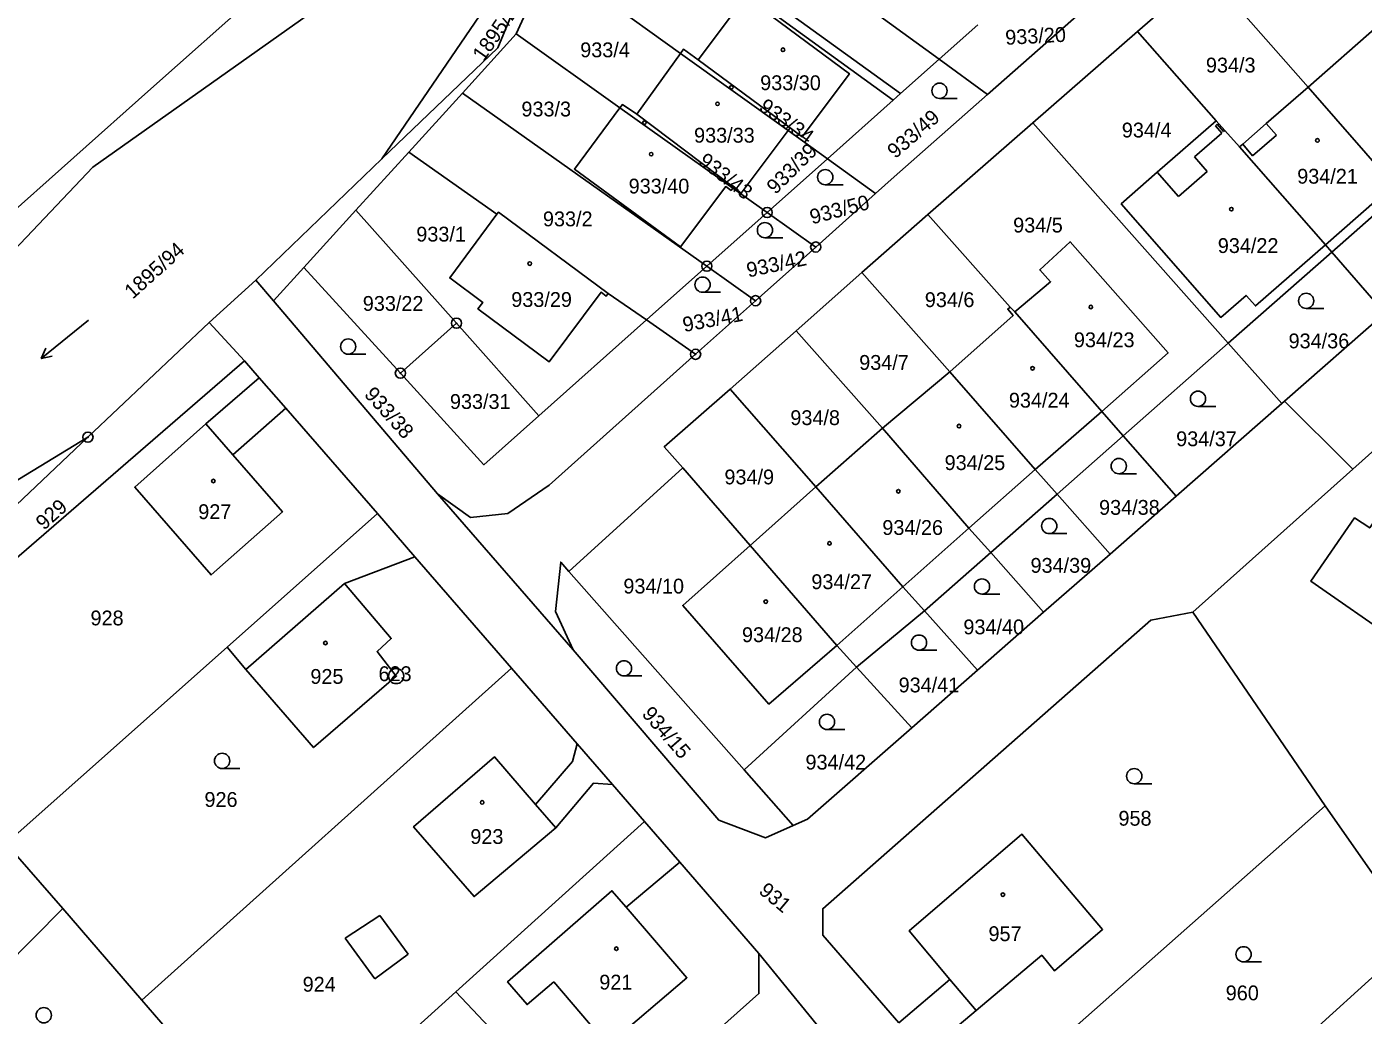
# Model space of a CAD drawing. Extents: x -587171 to -555306, y -1167727 to -1074732.
# Drawn here: x -560285.3 to -560153.7, y -1077555.8 to -1077458.5 of the extents above; entities that cross this region are included whole.
import ezdxf

# ---------------------------------------------------------------- set-up
doc = ezdxf.new("R2010")
doc.units = 0
for name, color, linetype in [('Hranice parcel', 7, 'Continuous'), ('Parcelní čísla', 7, 'Continuous'), ('Vnitřní kresba', 7, 'Continuous'), ('Značky bodu BP', 7, 'Continuous'), ('Značky budov', 7, 'Continuous'), ('Značky kultur', 7, 'Continuous')]:
    doc.layers.add(name, color=color, linetype=linetype)

msp = doc.modelspace()

# ---------------------------------------------------------------- linework, layer by layer
at = {"layer": 'Hranice parcel'}
for p, q in [((-560195.5, -1077461.65), (-560227.6, -1077438.32)), ((-560229.75, -1077443), (-560199.31, -1077465.04)), ((-560200.02, -1077465.68), (-560230.15, -1077443.87)), ((-560237.17, -1077459.16), (-560233.82, -1077451.86)), ((-560220.97, -1077461.08), (-560233.82, -1077451.86)), ((-560273.13, -1077464.57), (-560260.86, -1077453.64)), ((-560175.99, -1077458.92), (-560169.18, -1077453.02)), ((-560169.18, -1077453.02), (-560159.18, -1077464.39)), ((-560190.74, -1077465.12), (-560179.7, -1077455.38)), ((-560195.5, -1077461.65), (-560191.69, -1077458.26)), ((-560186.28, -1077467.93), (-560175.99, -1077458.92)), ((-560175.99, -1077458.92), (-560168.22, -1077467.71)), ((-560159.18, -1077464.39), (-560152.39, -1077458.44)), ((-560242.45, -1077464.98), (-560237.17, -1077459.16)), ((-560226.94, -1077466.44), (-560237.17, -1077459.16)), ((-560225.28, -1077467.06), (-560220.97, -1077461.08)), ((-560210.38, -1077468.68), (-560220.97, -1077461.08)), ((-560219.22, -1077461.72), (-560210.18, -1077468.42)), ((-560199.31, -1077465.04), (-560195.5, -1077461.65)), ((-560195.5, -1077461.65), (-560190.74, -1077465.12)), ((-560273.13, -1077464.57), (-560298.78, -1077487.41)), ((-560247.74, -1077470.8), (-560242.45, -1077464.98)), ((-560218.38, -1077482.04), (-560242.45, -1077464.98)), ((-560200.02, -1077465.68), (-560199.31, -1077465.04)), ((-560215.82, -1077474.34), (-560226.94, -1077466.44)), ((-560206.5, -1077471.46), (-560200.02, -1077465.68)), ((-560225.28, -1077467.06), (-560215.76, -1077474.25)), ((-560196.61, -1077476.96), (-560186.28, -1077467.93)), ((-560186.28, -1077467.93), (-560167.04, -1077489.63)), ((-560210.18, -1077468.42), (-560210.38, -1077468.68)), ((-560210.38, -1077468.68), (-560206.5, -1077471.46)), ((-560252.95, -1077476.52), (-560247.74, -1077470.8)), ((-560239.05, -1077476.93), (-560247.74, -1077470.8)), ((-560165.93, -1077470.29), (-560157.48, -1077479.93)), ((-560250.37, -1077471.48), (-560262.78, -1077483.42)), ((-560212.44, -1077476.75), (-560206.5, -1077471.46)), ((-560206.5, -1077471.46), (-560201.76, -1077474.87)), ((-560154.78, -1077502.03), (-560122.01, -1077472.74)), ((-560215.76, -1077474.25), (-560215.82, -1077474.34)), ((-560212.44, -1077476.75), (-560215.82, -1077474.34)), ((-560156.85, -1077480.65), (-560150.14, -1077474.73)), ((-560201.76, -1077474.87), (-560207.66, -1077480.15)), ((-560258.07, -1077482.16), (-560252.95, -1077476.52)), ((-560252.95, -1077476.52), (-560243.03, -1077487.66)), ((-560218.38, -1077482.04), (-560212.44, -1077476.75)), ((-560207.66, -1077480.15), (-560212.44, -1077476.75)), ((-560203.12, -1077482.67), (-560196.61, -1077476.96)), ((-560196.61, -1077476.96), (-560188.5, -1077486.06)), ((-560156.85, -1077480.65), (-560157.48, -1077479.93)), ((-560207.66, -1077480.15), (-560213.58, -1077485.44)), ((-560167.04, -1077489.63), (-560156.85, -1077480.65)), ((-560156.85, -1077480.65), (-560151.61, -1077486.65)), ((-560261.05, -1077485.45), (-560258.07, -1077482.16)), ((-560258.07, -1077482.16), (-560248.56, -1077492.58)), ((-560224.31, -1077487.32), (-560218.38, -1077482.04)), ((-560213.58, -1077485.44), (-560218.38, -1077482.04)), ((-560209.6, -1077488.41), (-560203.12, -1077482.67)), ((-560203.12, -1077482.67), (-560194.46, -1077492.43)), ((-560262.78, -1077483.42), (-560267.37, -1077487.58)), ((-560261.05, -1077485.45), (-560262.78, -1077483.42)), ((-560224.31, -1077487.32), (-560228.1, -1077484.74)), ((-560244.9, -1077504.45), (-560261.05, -1077485.45)), ((-560213.58, -1077485.44), (-560219.49, -1077490.72)), ((-560188.5, -1077486.06), (-560188.04, -1077486.53)), ((-560188.04, -1077486.53), (-560179.49, -1077496.34)), ((-560151.61, -1077486.65), (-560161.51, -1077495.35)), ((-560267.37, -1077487.58), (-560279.32, -1077498.88)), ((-560263.92, -1077491.36), (-560267.37, -1077487.58)), ((-560248.56, -1077492.58), (-560243.03, -1077487.66)), ((-560243.03, -1077487.66), (-560234.91, -1077496.77)), ((-560234.91, -1077496.77), (-560224.31, -1077487.32)), ((-560219.49, -1077490.72), (-560224.31, -1077487.32)), ((-560216.09, -1077494.16), (-560209.6, -1077488.41)), ((-560209.6, -1077488.41), (-560201.09, -1077497.99)), ((-560177.38, -1077498.75), (-560167.04, -1077489.63)), ((-560167.04, -1077489.63), (-560161.77, -1077495.57)), ((-560263.92, -1077491.36), (-560300.86, -1077523.32)), ((-560262.47, -1077493.02), (-560263.92, -1077491.36)), ((-560219.49, -1077490.72), (-560233.92, -1077503.62)), ((-560259.85, -1077496.04), (-560262.47, -1077493.02)), ((-560201.09, -1077497.99), (-560194.46, -1077492.43)), ((-560216.09, -1077494.16), (-560207.66, -1077503.77)), ((-560161.77, -1077495.57), (-560172.18, -1077504.7)), ((-560161.51, -1077495.35), (-560161.77, -1077495.57)), ((-560250.82, -1077506.4), (-560259.85, -1077496.04)), ((-560179.49, -1077496.34), (-560177.38, -1077498.75)), ((-560207.66, -1077503.77), (-560201.09, -1077497.99)), ((-560279.32, -1077498.88), (-560302.8, -1077521.08)), ((-560183.9, -1077504.49), (-560177.38, -1077498.75)), ((-560177.38, -1077498.75), (-560172.18, -1077504.7)), ((-560231.97, -1077512.1), (-560220.76, -1077501.91)), ((-560220.76, -1077501.91), (-560214.1, -1077509.55)), ((-560170.54, -1077516.12), (-560154.78, -1077502.03)), ((-560231.56, -1077519.83), (-560244.9, -1077504.45)), ((-560214.1, -1077509.55), (-560207.66, -1077503.77)), ((-560190.43, -1077510.25), (-560183.9, -1077504.49)), ((-560183.9, -1077504.49), (-560178.67, -1077510.39)), ((-560172.18, -1077504.7), (-560178.67, -1077510.39)), ((-560250.82, -1077506.4), (-560265.62, -1077519.56)), ((-560247.12, -1077510.67), (-560250.82, -1077506.4)), ((-560214.1, -1077509.55), (-560205.58, -1077519.4)), ((-560196.95, -1077516), (-560190.43, -1077510.25)), ((-560190.43, -1077510.25), (-560185.22, -1077516.13)), ((-560237.62, -1077521.64), (-560247.12, -1077510.67)), ((-560178.67, -1077510.39), (-560185.22, -1077516.13)), ((-560231.97, -1077512.1), (-560214.71, -1077531.65)), ((-560203.65, -1077521.52), (-560196.95, -1077516)), ((-560196.95, -1077516), (-560191.74, -1077521.84)), ((-560185.22, -1077516.13), (-560191.74, -1077521.84)), ((-560170.54, -1077516.12), (-560157.51, -1077535.21)), ((-560203.65, -1077521.52), (-560205.58, -1077519.4)), ((-560265.62, -1077519.56), (-560287.37, -1077538.9)), ((-560237.62, -1077521.64), (-560274.02, -1077554.33)), ((-560231.16, -1077529.09), (-560237.62, -1077521.64)), ((-560214.71, -1077531.65), (-560203.65, -1077521.52)), ((-560203.65, -1077521.52), (-560198.21, -1077527.51)), ((-560191.74, -1077521.84), (-560198.21, -1077527.51)), ((-560227.68, -1077533.09), (-560231.16, -1077529.09)), ((-560209.87, -1077537.13), (-560214.71, -1077531.65)), ((-560224.51, -1077536.75), (-560227.68, -1077533.09)), ((-560191.75, -1077565.49), (-560157.51, -1077535.21)), ((-560157.51, -1077535.21), (-560148.96, -1077547.42)), ((-560224.51, -1077536.75), (-560243.11, -1077553.53)), ((-560221.04, -1077540.75), (-560224.51, -1077536.75)), ((-560281.79, -1077545.31), (-560287.37, -1077538.9)), ((-560213.26, -1077549.74), (-560221.04, -1077540.75)), ((-560274.02, -1077554.33), (-560281.79, -1077545.31)), ((-560199.49, -1077556.57), (-560206.96, -1077547.95)), ((-560181.09, -1077577.69), (-560148.82, -1077548.43)), ((-560199.75, -1077566.27), (-560213.26, -1077549.74)), ((-560243.11, -1077553.53), (-560260.72, -1077569.43)), ((-560270.26, -1077558.67), (-560274.02, -1077554.33))]:
    msp.add_line(p, q, dxfattribs=at)
for points in [[(-560214.76, -1077410.16), (-560235.05, -1077451.08), (-560238.97, -1077460.52), (-560250.37, -1077471.48)], [(-560344.11, -1077542.98), (-560322.5, -1077519.89), (-560300.89, -1077495.53), (-560278.85, -1077472.29), (-560254.7, -1077455.13), (-560250.95, -1077451.74), (-560235.79, -1077431.89)], [(-560231.69, -1077442.28), (-560235.75, -1077449.99), (-560250.37, -1077471.48)], [(-560219.22, -1077461.72), (-560214.58, -1077455.47), (-560204.35, -1077463.08), (-560209.01, -1077469.29), (-560210.18, -1077468.42)], [(-560220.97, -1077461.08), (-560220.67, -1077460.65), (-560219.22, -1077461.72)], [(-560190.74, -1077465.12), (-560199.94, -1077473.24), (-560201.76, -1077474.87)], [(-560165.93, -1077470.29), (-560165.62, -1077470.03), (-560163.3, -1077467.99), (-560159.18, -1077464.39)], [(-560159.18, -1077464.39), (-560150.76, -1077474.02), (-560150.14, -1077474.73)], [(-560215.82, -1077474.34), (-560215.99, -1077474.58), (-560216.52, -1077474.2), (-560220.97, -1077480.14), (-560231.42, -1077472.47), (-560226.94, -1077466.44)], [(-560226.94, -1077466.44), (-560226.7, -1077466.12), (-560225.28, -1077467.06)], [(-560157.48, -1077479.93), (-560164.36, -1077485.95), (-560165.28, -1077484.91), (-560167.78, -1077487.09), (-560177.57, -1077475.9), (-560174.03, -1077472.79), (-560168.22, -1077467.71)], [(-560168.22, -1077467.71), (-560167.37, -1077468.66), (-560165.93, -1077470.29)], [(-560215.76, -1077474.25), (-560214.99, -1077474.83), (-560210.38, -1077468.68)], [(-560228.1, -1077484.74), (-560228.28, -1077484.99), (-560228.8, -1077484.6), (-560233.91, -1077491.47), (-560240.93, -1077486.23), (-560240.45, -1077485.61), (-560243.7, -1077483.2), (-560239.05, -1077476.93)], [(-560239.05, -1077476.93), (-560238.9, -1077476.73), (-560228.1, -1077484.74)], [(-560188.04, -1077486.53), (-560184.54, -1077483.57), (-560185.61, -1077482.4), (-560182.62, -1077479.63), (-560172.96, -1077490.59), (-560179.49, -1077496.34)], [(-560194.46, -1077492.43), (-560188.22, -1077486.88), (-560188.75, -1077486.27), (-560188.5, -1077486.06)], [(-560262.47, -1077493.02), (-560267.72, -1077497.56), (-560274.71, -1077503.79), (-560267.19, -1077512.45), (-560260.18, -1077506.22), (-560265.06, -1077500.61), (-560259.85, -1077496.04)], [(-560248.56, -1077492.58), (-560240.33, -1077501.59), (-560234.91, -1077496.77)], [(-560194.46, -1077492.43), (-560186.04, -1077502.08), (-560183.9, -1077504.49)], [(-560220.76, -1077501.91), (-560222.57, -1077499.83), (-560216.09, -1077494.16)], [(-560154.78, -1077502.03), (-560155.11, -1077501.7), (-560161.51, -1077495.35)], [(-560201.09, -1077497.99), (-560192.57, -1077507.84), (-560190.43, -1077510.25)], [(-560279.32, -1077498.88), (-560322.75, -1077525.36), (-560344.11, -1077542.98)], [(-560147.31, -1077502.53), (-560148.82, -1077501.54), (-560153.11, -1077507.82), (-560154.6, -1077506.84), (-560158.9, -1077513.07), (-560150.41, -1077518.96), (-560145.99, -1077512.72), (-560144.51, -1077513.73), (-560140.23, -1077507.47)], [(-560233.92, -1077503.62), (-560237.97, -1077506.39), (-560241.66, -1077506.79), (-560244.9, -1077504.45)], [(-560207.66, -1077503.77), (-560199.08, -1077513.62), (-560196.95, -1077516)], [(-560205.58, -1077519.4), (-560212.27, -1077525.17), (-560220.76, -1077515.46), (-560214.1, -1077509.55)], [(-560265.62, -1077519.56), (-560263.78, -1077521.77), (-560257.11, -1077529.45), (-560248.97, -1077522.41), (-560250.85, -1077520), (-560249.45, -1077518.72), (-560254.07, -1077513.3), (-560247.12, -1077510.67)], [(-560231.56, -1077519.83), (-560233.27, -1077516.04), (-560232.77, -1077511.18), (-560231.97, -1077512.1)], [(-560206.96, -1077547.95), (-560206.97, -1077545.34), (-560174.65, -1077516.92), (-560170.54, -1077516.12)], [(-560209.87, -1077537.13), (-560212.61, -1077538.36), (-560217.19, -1077536.61), (-560231.56, -1077519.83)], [(-560198.21, -1077527.51), (-560208.48, -1077536.51), (-560209.87, -1077537.13)], [(-560231.16, -1077529.09), (-560231.6, -1077530.83), (-560235.25, -1077535.05), (-560239.29, -1077530.38), (-560247.26, -1077537.26), (-560241.3, -1077544.14), (-560233.24, -1077537.37), (-560229.55, -1077532.97), (-560227.68, -1077533.09)], [(-560196.87, -1077559.58), (-560191.86, -1077555.36), (-560185.4, -1077549.92), (-560184.14, -1077551.46), (-560179.41, -1077547.36), (-560187.35, -1077537.99), (-560198.47, -1077547.52), (-560194.44, -1077552.3), (-560199.49, -1077556.57)], [(-560243.11, -1077553.53), (-560233.23, -1077563.99), (-560228.13, -1077558.76), (-560220.34, -1077552.13), (-560226.33, -1077545.19), (-560221.04, -1077540.75)], [(-560285.34, -1077573.49), (-560297.87, -1077561.55), (-560287.62, -1077551.2), (-560281.79, -1077545.31)], [(-560247.77, -1077584.47), (-560213.26, -1077553.69), (-560213.26, -1077549.74)]]:
    msp.add_lwpolyline(points, dxfattribs=at)
at = {"layer": 'Vnitřní kresba'}
for p, q in [((-560168.12, -1077468.06), (-560168.3, -1077468.22)), ((-560168.3, -1077468.22), (-560167.68, -1077468.93)), ((-560167.5, -1077468.77), (-560168.12, -1077468.06)), ((-560162.3, -1077469.12), (-560163.3, -1077467.99)), ((-560167.68, -1077468.93), (-560170.37, -1077471.28)), ((-560167.37, -1077468.66), (-560167.5, -1077468.77)), ((-560164.64, -1077471.16), (-560162.3, -1077469.12)), ((-560165.62, -1077470.03), (-560164.64, -1077471.16)), ((-560170.37, -1077471.28), (-560169.11, -1077472.71)), ((-560171.94, -1077475.18), (-560174.03, -1077472.79)), ((-560169.11, -1077472.71), (-560171.94, -1077475.18)), ((-560150.76, -1077474.02), (-560157.48, -1077479.93)), ((-560179.49, -1077496.34), (-560186.04, -1077502.08)), ((-560267.72, -1077497.56), (-560265.06, -1077500.61)), ((-560186.04, -1077502.08), (-560192.57, -1077507.84)), ((-560192.57, -1077507.84), (-560199.08, -1077513.62)), ((-560254.07, -1077513.3), (-560263.78, -1077521.77)), ((-560199.08, -1077513.62), (-560205.58, -1077519.4)), ((-560235.25, -1077535.05), (-560233.24, -1077537.37)), ((-560254.01, -1077548.22), (-560250.59, -1077546)), ((-560250.59, -1077546), (-560247.78, -1077549.81)), ((-560251.08, -1077552.25), (-560254.01, -1077548.22)), ((-560247.78, -1077549.81), (-560251.08, -1077552.25)), ((-560194.44, -1077552.3), (-560191.86, -1077555.36)), ((-560233.46, -1077552.54), (-560228.13, -1077558.76))]:
    msp.add_line(p, q, dxfattribs=at)
msp.add_lwpolyline([(-560233.46, -1077552.54), (-560236.08, -1077554.78), (-560238.01, -1077552.53), (-560227.73, -1077543.56), (-560226.33, -1077545.19)], dxfattribs=at)
at = {"layer": 'Značky bodu BP'}
for centre, radius in [((-560212.44, -1077476.75), 0.5), ((-560212.44, -1077476.75), 0.0303), ((-560207.66, -1077480.15), 0.5), ((-560207.66, -1077480.15), 0.0303), ((-560218.38, -1077482.04), 0.5), ((-560218.38, -1077482.04), 0.0303), ((-560213.58, -1077485.44), 0.5), ((-560213.58, -1077485.44), 0.0303), ((-560243.03, -1077487.66), 0.5), ((-560243.03, -1077487.66), 0.0303), ((-560219.49, -1077490.72), 0.5), ((-560219.49, -1077490.72), 0.0303), ((-560248.56, -1077492.58), 0.5), ((-560248.56, -1077492.58), 0.0303), ((-560279.32, -1077498.88), 0.5), ((-560279.32, -1077498.88), 0.0303), ((-560248.97, -1077522.41), 0.75), ((-560248.97, -1077522.41), 0.03)]:
    msp.add_circle(centre, radius, dxfattribs=at)
at = {"layer": 'Značky budov'}
for centre in [(-560210.89, -1077460.72), (-560215.96, -1077464.42), (-560217.33, -1077466.05), (-560224.52, -1077467.9), (-560158.26, -1077469.65), (-560223.86, -1077471.01), (-560166.73, -1077476.42), (-560235.82, -1077481.78), (-560180.57, -1077486.06), (-560186.31, -1077492.1), (-560193.55, -1077497.79), (-560266.97, -1077503.2), (-560199.52, -1077504.21), (-560206.3, -1077509.34), (-560212.58, -1077515.08), (-560255.94, -1077519.16), (-560240.51, -1077534.86), (-560189.23, -1077543.94), (-560227.29, -1077549.27)]:
    msp.add_circle(centre, 0.175, dxfattribs=at)
at = {"layer": 'Značky kultur'}
for p, q in [((-560195.47, -1077465.51), (-560193.72, -1077465.51)), ((-560206.72, -1077474.02), (-560204.97, -1077474.02)), ((-560212.66, -1077479.24), (-560210.91, -1077479.24)), ((-560218.8, -1077484.61), (-560217.05, -1077484.61)), ((-560159.37, -1077486.2), (-560157.62, -1077486.2)), ((-560279.26, -1077487.36), (-560283.92, -1077491.13)), ((-560283.92, -1077491.13), (-560283.48, -1077490.13)), ((-560283.92, -1077491.13), (-560282.84, -1077490.91)), ((-560253.7, -1077490.71), (-560251.95, -1077490.71)), ((-560170.02, -1077495.85), (-560168.27, -1077495.85)), ((-560177.82, -1077502.48), (-560176.07, -1077502.48)), ((-560184.67, -1077508.38), (-560182.92, -1077508.38)), ((-560191.29, -1077514.34), (-560189.54, -1077514.34)), ((-560197.49, -1077519.87), (-560195.74, -1077519.87)), ((-560226.54, -1077522.4), (-560224.79, -1077522.4)), ((-560206.55, -1077527.68), (-560204.8, -1077527.68)), ((-560266.11, -1077531.52), (-560264.36, -1077531.52)), ((-560176.3, -1077533.02), (-560174.55, -1077533.02)), ((-560165.53, -1077550.57), (-560163.78, -1077550.57))]:
    msp.add_line(p, q, dxfattribs=at)
for centre in [(-560195.47, -1077464.76), (-560206.72, -1077473.27), (-560212.66, -1077478.49), (-560218.8, -1077483.86), (-560159.37, -1077485.45), (-560253.7, -1077489.96), (-560170.02, -1077495.1), (-560177.82, -1077501.73), (-560184.67, -1077507.63), (-560191.29, -1077513.59), (-560197.49, -1077519.12), (-560226.54, -1077521.65), (-560206.55, -1077526.93), (-560266.11, -1077530.77), (-560176.3, -1077532.27), (-560165.53, -1077549.82), (-560283.67, -1077555.82)]:
    msp.add_circle(centre, 0.75, dxfattribs=at)

# ---------------------------------------------------------------- texts
at = {"layer": 'Parcelní čísla'}
for s, rotation, p in [('1895/20', 55, (-560240.37, -1077461.96)), ('933/20', 3, (-560188.96, -1077460.24)), ('933/34', 324, (-560213.36, -1077466.59)), ('933/49', 41, (-560199.83, -1077471.51)), ('933/39', 45, (-560211.62, -1077475.04)), ('933/43', 322, (-560219.32, -1077471.9)), ('933/50', 15, (-560208.02, -1077477.93)), ('1895/94', 42, (-560274.92, -1077485.35)), ('933/42', 12, (-560214.3, -1077483.16)), ('933/41', 11, (-560220.61, -1077488.54)), ('933/38', 312, (-560252.2, -1077494.73)), ('929', 42, (-560283.65, -1077508.11)), ('934/15', 311, (-560224.86, -1077526.19)), ('931', 320, (-560213.36, -1077543.73))]:
    msp.add_text(s, height=1.46, rotation=rotation, dxfattribs=at).set_placement(p)
for s, p in [('933/4', (-560230.85, -1077461.46)), ('934/3', (-560169.24, -1077462.96)), ('933/30', (-560213.13, -1077464.7)), ('933/3', (-560236.64, -1077467.29)), ('934/4', (-560177.52, -1077469.36)), ('933/33', (-560219.64, -1077469.87)), ('933/40', (-560226.08, -1077474.88)), ('934/21', (-560160.25, -1077473.91)), ('933/2', (-560234.52, -1077478.11)), ('934/5', (-560188.22, -1077478.72)), ('933/1', (-560246.99, -1077479.61)), ('934/22', (-560168.07, -1077480.74)), ('933/22', (-560252.26, -1077486.44)), ('933/29', (-560237.64, -1077486.05)), ('934/6', (-560196.92, -1077486.07)), ('934/23', (-560182.24, -1077490.02)), ('934/36', (-560161.1, -1077490.13)), ('934/7', (-560203.38, -1077492.25)), ('934/24', (-560188.64, -1077495.97)), ('933/31', (-560243.68, -1077496.1)), ('934/8', (-560210.16, -1077497.69)), ('934/37', (-560172.17, -1077499.77)), ('934/25', (-560194.97, -1077502.12)), ('934/9', (-560216.65, -1077503.53)), ('934/38', (-560179.76, -1077506.53)), ('927', (-560268.46, -1077506.95)), ('934/26', (-560201.1, -1077508.51)), ('934/39', (-560186.51, -1077512.24)), ('934/10', (-560226.6, -1077514.28)), ('934/27', (-560208.09, -1077513.85)), ('928', (-560279.07, -1077517.42)), ('934/40', (-560193.12, -1077518.3)), ('934/28', (-560214.92, -1077519.07)), ('925', (-560257.42, -1077523.18)), ('934/41', (-560199.5, -1077524.02)), ('934/42', (-560208.67, -1077531.62)), ('926', (-560267.85, -1077535.3)), ('958', (-560177.85, -1077537.15)), ('923', (-560241.67, -1077538.95)), ('957', (-560190.65, -1077548.52)), ('924', (-560258.18, -1077553.5)), ('921', (-560228.97, -1077553.29)), ('960', (-560167.29, -1077554.35))]:
    msp.add_text(s, height=1.46, dxfattribs=at).set_placement(p)
at = {"layer": 'Značky bodu BP'}
msp.add_text('623', height=1.46, dxfattribs=at).set_placement((-560250.71, -1077522.91))

doc.saveas('drawing.dxf')
